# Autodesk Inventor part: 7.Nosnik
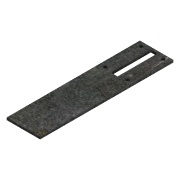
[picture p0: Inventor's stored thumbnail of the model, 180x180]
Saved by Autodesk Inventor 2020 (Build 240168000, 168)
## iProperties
Created: 2022-03
Part Number: 7.Nosnik
Material: Steel
Document SubType Name: Modeling
Designer: marti
Density: 7.85 g/cm^3
Appearance: Plate
Author: marti
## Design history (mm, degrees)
sketch "Sketch1"
  geometry: L1 (15, 60)-(-15, 60); L2 (-15, 60)-(-15, -60); L3 (-15, -60)-(15, -60); L4 (15, -60)-(15, 60); L5 (15, 60)-(-15, -60); L6 (-15, 60)-(15, -60); 1 further point
  constraints: 12 end point, 2 midpoint, 2 parallel, 1 horizontal, 1 perpendicular
  dimensions: "d0" = 30 distance of L3.end L2.end; "d1" = 120 distance of L2.end L1.end
extrude "Extrusion1" new body sketch "Sketch1" distance "d2" = 2; taper "d3" = 0 deg
sketch "Sketch2"
  geometry: L1 (15, 60)-(-15, 60) reference; L2 (0, 60)-(0, 57.9); L3 (0, 57.9)-(-3, 57.9); L4 (-3, 57.9)-(3, 57.9); L5 (3, 57.9)-(3, 21.9); L6 (3, 21.9)-(-3, 21.9); L7 (-3, 21.9)-(-3, 57.9); 2 further points
  constraints: 12 end point, 2 parallel, 2 perpendicular, 1 horizontal, 1 midpoint, 1 vertical
  dimensions: "d4" = 2.1 distance of L2.start L2.end; "d5" = 3 distance of L2.end L3.end; "d6" = 6 distance of L5.end L6.end; "d7" = 36 distance of L4.end L5.end
extrude "Extrusion2" cut sketch "Sketch2" distance "d8" = 2; taper "d9" = 0 deg
sketch "Sketch3"
  geometry: L1 (15, -60)-(15, 60) reference; L2 (15, 60)-(-15, 60) reference; C1 r 1.5 at (10, 56); 1 further point
  constraints: 1 centre point
  dimensions: "d10" = 3 diameter of C1; "d11" = 5 distance from line of L1 C1.centre; "d12" = 4 distance from line of C1.centre L2
extrude "Extrusion3" cut sketch "Sketch3" distance "d13" = 2; taper "d14" = 0 deg
pattern_linear "Rectangular Pattern1" dims "d17" = 20
pattern_linear "Rectangular Pattern2" dims "d20" = 32.2
body "Solid1"
